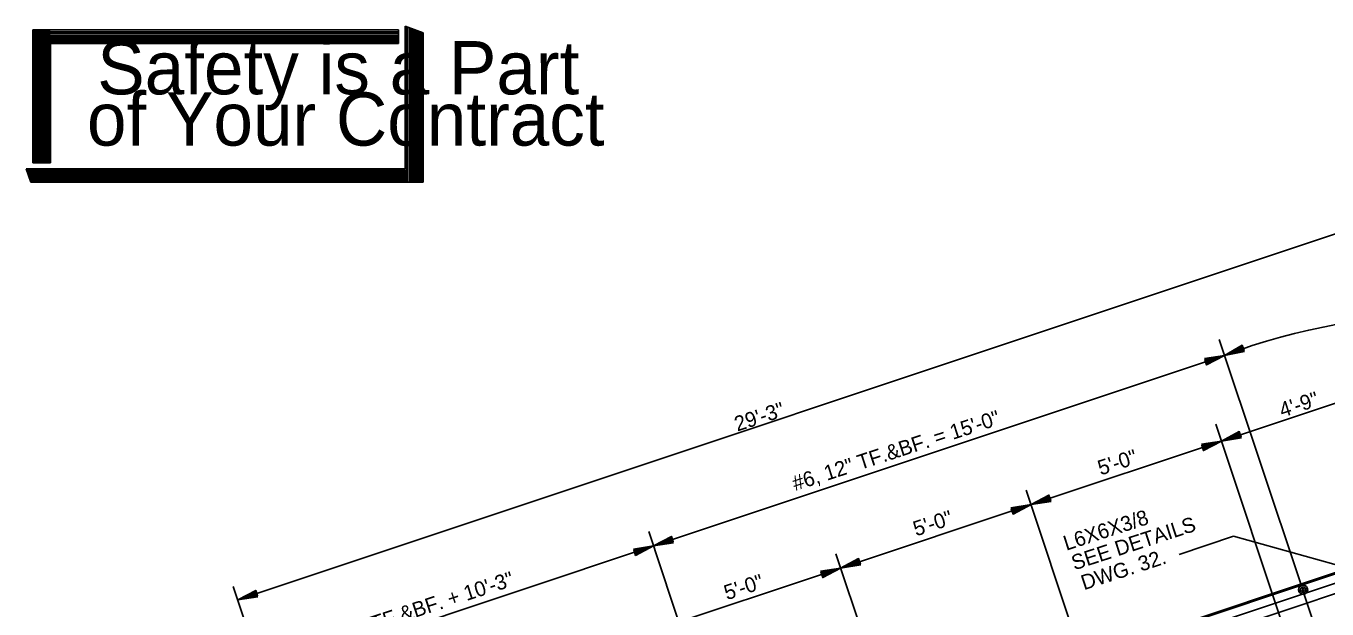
# Model space of a CAD drawing. Extents: x 6 to 106, y 3 to 74.
# Drawn here: x 5.62 to 38.04, y 59.54 to 74.05 of the extents above; entities that cross this region are included whole.
import ezdxf

# ---------------------------------------------------------------- set-up
doc = ezdxf.new("R2010")
doc.units = 0
for name, color, linetype in [('Level 1', 7, 'Continuous'), ('Level 22', 7, 'Continuous'), ('Level 25', 7, 'Continuous'), ('Level 50', 7, 'Continuous')]:
    doc.layers.add(name, color=color, linetype=linetype)

msp = doc.modelspace()

# ---------------------------------------------------------------- linework, layer by layer
at = {"layer": 'Level 1'}
for p, q in [((5.793, 73.954), (14.905, 73.954)), ((5.793, 73.954), (5.793, 70.644)), ((5.793, 73.911), (14.905, 73.911)), ((5.835, 73.954), (5.835, 70.644)), ((5.875, 73.954), (5.875, 70.644)), ((5.918, 73.954), (5.918, 70.644)), ((5.958, 73.954), (5.958, 70.644)), ((6.001, 73.954), (6.001, 70.644)), ((6.043, 73.954), (6.043, 70.644)), ((6.083, 73.954), (6.083, 70.644)), ((6.126, 73.954), (6.126, 70.644)), ((6.169, 73.954), (6.169, 70.644)), ((6.209, 73.954), (6.209, 70.644)), ((14.905, 73.954), (14.905, 73.62)), ((15.073, 74.052), (15.073, 70.495)), ((15.073, 74.052), (15.518, 73.887)), ((15.102, 74.042), (15.102, 70.162)), ((15.142, 74.026), (15.142, 70.162)), ((15.185, 74.01), (15.185, 70.162)), ((15.227, 73.994), (15.227, 70.162)), ((15.267, 73.98), (15.267, 70.162)), ((15.31, 73.964), (15.31, 70.162)), ((15.35, 73.948), (15.35, 70.162)), ((15.393, 73.932), (15.393, 70.162)), ((15.435, 73.919), (15.435, 70.162)), ((5.793, 73.871), (14.905, 73.871)), ((5.793, 73.828), (14.905, 73.828)), ((5.793, 73.786), (14.905, 73.786)), ((5.793, 73.746), (14.905, 73.746)), ((5.793, 73.703), (14.905, 73.703)), ((5.793, 73.663), (14.905, 73.663)), ((6.238, 73.62), (14.905, 73.62)), ((6.238, 73.62), (6.238, 70.644)), ((15.475, 73.887), (15.475, 70.162)), ((15.518, 73.887), (15.518, 70.162)), ((5.625, 70.495), (15.073, 70.495)), ((5.625, 70.495), (5.747, 70.162)), ((5.641, 70.452), (15.102, 70.452)), ((5.654, 70.412), (15.102, 70.412)), ((5.67, 70.37), (15.102, 70.37)), ((5.793, 70.644), (6.238, 70.644)), ((5.686, 70.327), (15.102, 70.327)), ((5.702, 70.287), (15.102, 70.287)), ((5.718, 70.244), (15.102, 70.244)), ((5.731, 70.204), (15.102, 70.204)), ((5.747, 70.162), (15.518, 70.162))]:
    msp.add_line(p, q, dxfattribs=at)
at = {"layer": 'Level 22'}
msp.add_line((35.712, 61.347), (38.565, 60.552), dxfattribs=at)
msp.add_arc((41.18, 50.691), 16.194, 69.4208, 110.5793, dxfattribs=at)
at = {"layer": 'Level 25'}
for p, q in [((10.902, 59.764), (38.651, 69.013)), ((37.386, 60.159), (35.357, 66.246)), ((21.258, 61.108), (35.488, 65.851)), ((35.409, 63.716), (39.916, 65.219)), ((37.149, 58.499), (35.27, 64.135)), ((30.666, 62.135), (35.409, 63.716)), ((32.405, 56.918), (30.545, 62.497)), ((25.922, 60.554), (30.666, 62.135)), ((14.561, 52.551), (41.18, 61.424)), ((20.588, 54.527), (41.19, 61.394)), ((23.155, 55.416), (21.14, 61.463)), ((34.355, 60.895), (35.712, 61.347)), ((11.534, 57.866), (21.258, 61.108)), ((14.835, 52.378), (41.18, 61.16)), ((20.736, 54.082), (41.18, 60.897)), ((27.662, 55.336), (25.803, 60.913)), ((21.179, 58.973), (25.922, 60.554)), ((13.817, 51.018), (10.789, 60.1)), ((39.833, 52.818), (37.44, 59.996))]:
    msp.add_line(p, q, dxfattribs=at)
at = {"layer": 'Level 50'}
for p, q in [((35.357, 65.807), (35.357, 65.807)), ((35.357, 65.807), (35.357, 65.807)), ((35.488, 65.851), (35.488, 65.851)), ((35.488, 65.851), (35.488, 65.851)), ((35.488, 65.851), (35.488, 65.851)), ((35.618, 65.9), (35.618, 65.9)), ((35.278, 63.673), (35.278, 63.673)), ((35.409, 63.716), (35.409, 63.716)), ((35.409, 63.716), (35.409, 63.716)), ((35.541, 63.76), (35.541, 63.76)), ((30.534, 62.091), (30.534, 62.091)), ((30.666, 62.135), (30.666, 62.135)), ((30.666, 62.135), (30.666, 62.135)), ((30.797, 62.179), (30.797, 62.179)), ((21.127, 61.064), (21.127, 61.064)), ((21.258, 61.108), (21.258, 61.108)), ((21.258, 61.108), (21.258, 61.108)), ((21.39, 61.151), (21.39, 61.151)), ((25.791, 60.51), (25.791, 60.51)), ((25.922, 60.554), (25.922, 60.554)), ((25.922, 60.554), (25.922, 60.554)), ((26.054, 60.598), (26.054, 60.598)), ((10.902, 59.764), (10.902, 59.764)), ((11.033, 59.807), (11.033, 59.807))]:
    msp.add_line(p, q, dxfattribs=at)
for points in [[(34.989, 65.772), (35.488, 65.851), (35.041, 65.615), (34.997, 65.749), (35.357, 65.807), (35.053, 65.647), (35.025, 65.733), (35.23, 65.765), (35.065, 65.679), (35.053, 65.714), (35.099, 65.721)], [(34.989, 65.772), (35.488, 65.851), (35.041, 65.615), (34.997, 65.749), (35.357, 65.807), (35.053, 65.647), (35.025, 65.733), (35.23, 65.765), (35.065, 65.679), (35.053, 65.714), (35.099, 65.721)], [(35.984, 65.949), (35.488, 65.851), (35.926, 66.104), (35.976, 65.971), (35.618, 65.9), (35.916, 66.071), (35.947, 65.986), (35.743, 65.947), (35.905, 66.039), (35.918, 66.004), (35.873, 65.995)], [(35.909, 63.796), (35.409, 63.716), (35.856, 63.953), (35.901, 63.818), (35.541, 63.76), (35.844, 63.921), (35.873, 63.835), (35.667, 63.802), (35.833, 63.888), (35.844, 63.853), (35.799, 63.846)], [(34.91, 63.637), (35.409, 63.716), (34.962, 63.48), (34.918, 63.614), (35.278, 63.673), (34.974, 63.512), (34.946, 63.598), (35.151, 63.63), (34.986, 63.544), (34.974, 63.58), (35.02, 63.587)], [(31.165, 62.215), (30.666, 62.135), (31.113, 62.371), (31.158, 62.237), (30.797, 62.179), (31.101, 62.339), (31.13, 62.253), (30.924, 62.221), (31.089, 62.307), (31.101, 62.272), (31.055, 62.265)], [(30.167, 62.056), (30.666, 62.135), (30.219, 61.899), (30.174, 62.033), (30.534, 62.091), (30.231, 61.931), (30.202, 62.017), (30.408, 62.049), (30.243, 61.963), (30.231, 61.999), (30.276, 62.005)], [(21.757, 61.187), (21.258, 61.108), (21.705, 61.344), (21.75, 61.21), (21.39, 61.151), (21.693, 61.312), (21.722, 61.226), (21.516, 61.194), (21.681, 61.28), (21.693, 61.244), (21.648, 61.237)], [(20.759, 61.028), (21.258, 61.108), (20.811, 60.871), (20.766, 61.006), (21.127, 61.064), (20.823, 60.904), (20.794, 60.99), (21, 61.022), (20.835, 60.936), (20.823, 60.971), (20.869, 60.978)], [(26.422, 60.633), (25.922, 60.554), (26.369, 60.79), (26.414, 60.656), (26.054, 60.598), (26.358, 60.758), (26.386, 60.672), (26.181, 60.64), (26.346, 60.726), (26.358, 60.691), (26.312, 60.684)], [(25.423, 60.475), (25.922, 60.554), (25.476, 60.318), (25.431, 60.452), (25.791, 60.51), (25.487, 60.35), (25.459, 60.436), (25.664, 60.468), (25.499, 60.382), (25.487, 60.418), (25.533, 60.424)], [(11.401, 59.843), (10.902, 59.764), (11.349, 60), (11.393, 59.866), (11.033, 59.807), (11.337, 59.968), (11.365, 59.882), (11.16, 59.85), (11.325, 59.936), (11.337, 59.9), (11.291, 59.893)]]:
    msp.add_lwpolyline(points, dxfattribs=at)
for radius in [0.113, 0.0703, 0.0281]:
    msp.add_circle((37.446, 60.017), radius, dxfattribs=at)

# ---------------------------------------------------------------- texts
at = {"layer": 'Level 1'}
for s, p in [('Safety is a Part', (7.4, 72.352)), ('of Your Contract', (7.143, 71.075))]:
    msp.add_text(s, height=1.32466, dxfattribs=at).set_placement(p)
at = {"layer": 'Level 22'}
for s, height, p in [('4\'-9"', 0.3733, (36.924, 64.3)), ('29\'-3"', 0.3733, (23.347, 63.953)), ('#6, 12" TF.&BF. = 15\'-0"', 0.37333, (24.788, 62.471)), ('5\'-0"', 0.3733, (32.401, 62.859)), ('5\'-0"', 0.3733, (27.801, 61.343)), ('L6X6X3/8', 0.3733, (31.544, 60.985)), ('SEE DETAILS ', 0.37333, (31.745, 60.497)), ('DWG. 32.', 0.3733, (31.984, 60.002)), ('#6, 6" TF.&BF. + 10\'-3"', 0.37333, (12.936, 58.543)), ('5\'-0"', 0.3733, (23.088, 59.753))]:
    msp.add_text(s, height=height, rotation=18, dxfattribs=at).set_placement(p)

doc.saveas('drawing.dxf')
